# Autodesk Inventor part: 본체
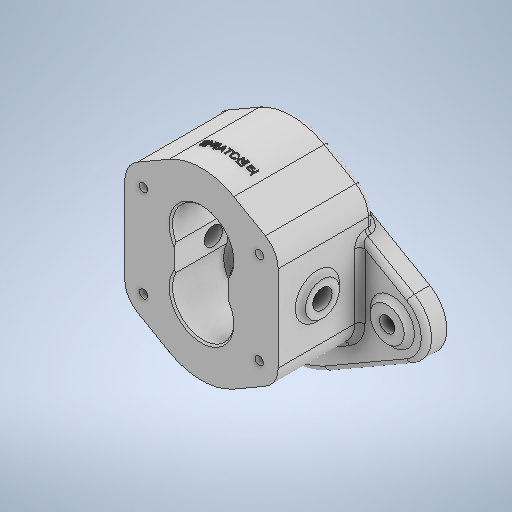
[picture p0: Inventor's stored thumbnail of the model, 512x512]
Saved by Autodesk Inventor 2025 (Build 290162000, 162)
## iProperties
Created: 2026-08
Part Number: 본체
Material: 알루미늄 6061
Document SubType Name: Modeling
Designer: KDI
Density: 2.7 g/cm^3
Appearance: 알루미늄 - 평지
Mass: 1251.84 g
Surface Area: 588.259 cm^2
Volume: 463.644 cm^3
Sending System: Autodesk Inventor 2027
Preprocessor: ST-DEVELOPER v20.1
Author: jhkim
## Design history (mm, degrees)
feature "솔리드1"
node "솔리드2"
